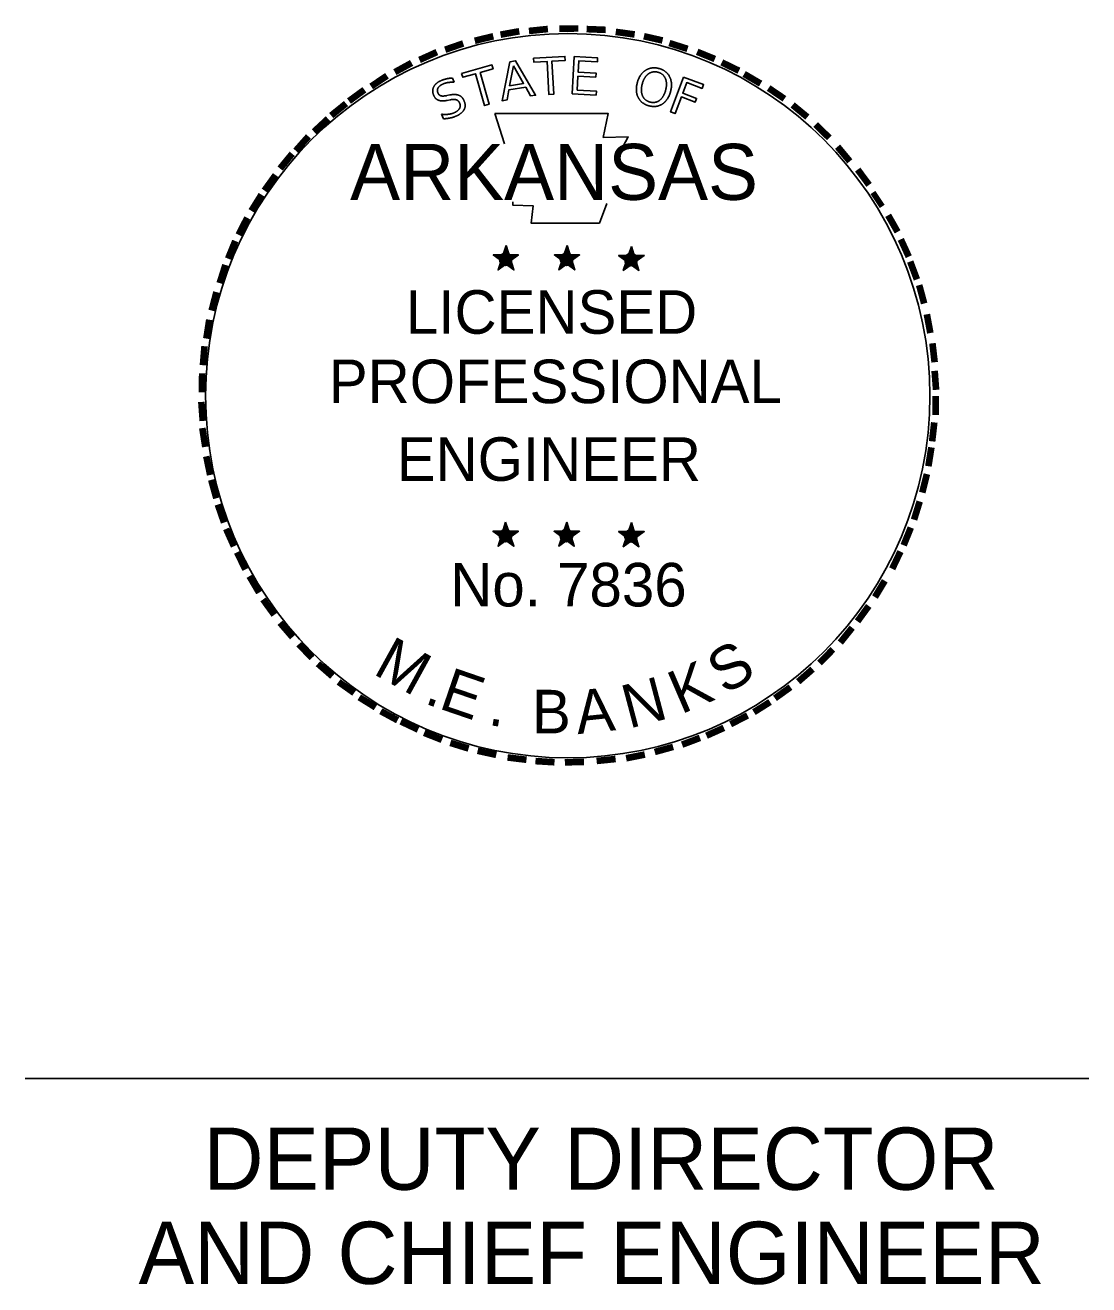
# Model space of a CAD drawing. Extents: x -0.25 to 1.92, y 0 to 0.95.
# Drawn here: x 1.7484 to 1.9193, y 0.0415 to 0.244 of the extents above; entities that cross this region are included whole.
import ezdxf

# ---------------------------------------------------------------- set-up
doc = ezdxf.new("R2010")
doc.units = 0
doc.layers.add('SHET_Stamp-PE-Chief-Eng', color=7, linetype='Continuous')

msp = doc.modelspace()

# ---------------------------------------------------------------- linework, layer by layer
at = {"layer": 'SHET_Stamp-PE-Chief-Eng'}
for p, q in [((1.85025, 0.23705), (1.85025, 0.23705)), ((1.81706, 0.23552), (1.81734, 0.23483)), ((1.85009, 0.23645), (1.85009, 0.23645)), ((1.81617, 0.23269), (1.81666, 0.23279)), ((1.81673, 0.23202), (1.81623, 0.23192)), ((1.81562, 0.22896), (1.81532, 0.2297)), ((1.82568, 0.20858), (1.82544, 0.20707)), ((1.82568, 0.20641), (1.82568, 0.20858)), ((1.82568, 0.20858), (1.82598, 0.20713)), ((1.83551, 0.20858), (1.83527, 0.20707)), ((1.83551, 0.20641), (1.83551, 0.20858)), ((1.83551, 0.20858), (1.83576, 0.20713)), ((1.82363, 0.20707), (1.82568, 0.20641)), ((1.82363, 0.20707), (1.82513, 0.20683)), ((1.82363, 0.20707), (1.82501, 0.20635)), ((1.82767, 0.20707), (1.82568, 0.20641)), ((1.82767, 0.20707), (1.82604, 0.20677)), ((1.82767, 0.20707), (1.82652, 0.20647)), ((1.83346, 0.20707), (1.83551, 0.20641)), ((1.83346, 0.20707), (1.83491, 0.20683)), ((1.83346, 0.20707), (1.83479, 0.20635)), ((1.83751, 0.20707), (1.83551, 0.20641)), ((1.83751, 0.20707), (1.83582, 0.20677)), ((1.83751, 0.20707), (1.8363, 0.20647)), ((1.84378, 0.20701), (1.84583, 0.20635)), ((1.84378, 0.20701), (1.84523, 0.20671)), ((1.84378, 0.20701), (1.84517, 0.20629)), ((1.84583, 0.20846), (1.84559, 0.20701)), ((1.84583, 0.20635), (1.84583, 0.20846)), ((1.84583, 0.20846), (1.84608, 0.20701)), ((1.84789, 0.20701), (1.84583, 0.20635)), ((1.84789, 0.20701), (1.84614, 0.20671)), ((1.84789, 0.20701), (1.84662, 0.20641)), ((1.82441, 0.20466), (1.82568, 0.20641)), ((1.82441, 0.20466), (1.82513, 0.20611)), ((1.82441, 0.20466), (1.82562, 0.20593)), ((1.82694, 0.20466), (1.82562, 0.20593)), ((1.82694, 0.20466), (1.82568, 0.20641)), ((1.82694, 0.20466), (1.8261, 0.20635)), ((1.83419, 0.20466), (1.83551, 0.20641)), ((1.83419, 0.20466), (1.83497, 0.20611)), ((1.83419, 0.20466), (1.83545, 0.20593)), ((1.83672, 0.20466), (1.83545, 0.20593)), ((1.83672, 0.20466), (1.83551, 0.20641)), ((1.83672, 0.20466), (1.83588, 0.20635)), ((1.84451, 0.2046), (1.84583, 0.20635)), ((1.84451, 0.2046), (1.84529, 0.20605)), ((1.84451, 0.2046), (1.84583, 0.20587)), ((1.84704, 0.2046), (1.84583, 0.20635)), ((1.84704, 0.2046), (1.84583, 0.20587)), ((1.84704, 0.2046), (1.84626, 0.20629)), ((1.82562, 0.1641), (1.82538, 0.16266)), ((1.82562, 0.16199), (1.82562, 0.1641)), ((1.82562, 0.1641), (1.82592, 0.16266)), ((1.83545, 0.1641), (1.83521, 0.16266)), ((1.83545, 0.16199), (1.83545, 0.1641)), ((1.83545, 0.1641), (1.8357, 0.16266)), ((1.84583, 0.16404), (1.84559, 0.1626)), ((1.84583, 0.16193), (1.84583, 0.16404)), ((1.84583, 0.16404), (1.84608, 0.1626)), ((1.82357, 0.16266), (1.82562, 0.16199)), ((1.82357, 0.16266), (1.82513, 0.16235)), ((1.82357, 0.16266), (1.82501, 0.16193)), ((1.82441, 0.16024), (1.82562, 0.16199)), ((1.82767, 0.16266), (1.82562, 0.16199)), ((1.82694, 0.16024), (1.82562, 0.16199)), ((1.82767, 0.16266), (1.82598, 0.16235)), ((1.82767, 0.16266), (1.82652, 0.16205)), ((1.8334, 0.16266), (1.83545, 0.16199)), ((1.8334, 0.16266), (1.83491, 0.16235)), ((1.8334, 0.16266), (1.83479, 0.16193)), ((1.83419, 0.16024), (1.83545, 0.16199)), ((1.83751, 0.16266), (1.83545, 0.16199)), ((1.83666, 0.16024), (1.83545, 0.16199)), ((1.83751, 0.16266), (1.83576, 0.16235)), ((1.83751, 0.16266), (1.83624, 0.16205)), ((1.84378, 0.1626), (1.84583, 0.16193)), ((1.84378, 0.1626), (1.84523, 0.16229)), ((1.84378, 0.1626), (1.84517, 0.16187)), ((1.84789, 0.1626), (1.84583, 0.16193)), ((1.84789, 0.1626), (1.84614, 0.16229)), ((1.84789, 0.1626), (1.84662, 0.16199)), ((1.82441, 0.16024), (1.82513, 0.16169)), ((1.82441, 0.16024), (1.82562, 0.16157)), ((1.82694, 0.16024), (1.82562, 0.16151)), ((1.82694, 0.16024), (1.8261, 0.16193)), ((1.83419, 0.16024), (1.83491, 0.16169)), ((1.83419, 0.16024), (1.83545, 0.16157)), ((1.83666, 0.16024), (1.83545, 0.16151)), ((1.83666, 0.16024), (1.83588, 0.16193)), ((1.84451, 0.16018), (1.84583, 0.16193)), ((1.84451, 0.16018), (1.84529, 0.16163)), ((1.84451, 0.16018), (1.84583, 0.16151)), ((1.84704, 0.16018), (1.84583, 0.16193)), ((1.84704, 0.16018), (1.84583, 0.16145)), ((1.84704, 0.16018), (1.8462, 0.16187)), ((1.74841, 0.07469), (1.91934, 0.07469))]:
    msp.add_line(p, q, dxfattribs=at)
for points in [[(1.83012, 0.23872), (1.83516, 0.23899), (1.8352, 0.23835), (1.83306, 0.23823), (1.83335, 0.23291), (1.83258, 0.23286), (1.83229, 0.23819), (1.83015, 0.23807)], [(1.83664, 0.23896), (1.8404, 0.23876), (1.84037, 0.23811), (1.83738, 0.23827), (1.83729, 0.23645), (1.84015, 0.2363), (1.84011, 0.23566), (1.83725, 0.23581), (1.83714, 0.23359), (1.8402, 0.23343), (1.84016, 0.23278), (1.83633, 0.23298)], [(1.81855, 0.23625), (1.82342, 0.23762), (1.82359, 0.237), (1.82153, 0.23642), (1.82298, 0.23129), (1.82223, 0.23108), (1.82078, 0.23621), (1.81873, 0.23563)], [(1.82632, 0.23814), (1.82504, 0.23187), (1.82584, 0.232), (1.82613, 0.23361), (1.82884, 0.23406), (1.82964, 0.23263), (1.83043, 0.23276), (1.82721, 0.23829)], [(1.82688, 0.2375), (1.8285, 0.23465), (1.82626, 0.23428)], [(1.85423, 0.23566), (1.85743, 0.23446), (1.8572, 0.23385), (1.85472, 0.23478), (1.85409, 0.23308), (1.85632, 0.23225), (1.8561, 0.23164), (1.85386, 0.23248), (1.85286, 0.22979), (1.85213, 0.23006)]]:
    msp.add_lwpolyline(points, close=True, dxfattribs=at)
for points in [[(1.82387, 0.22982), (1.82544, 0.22494)], [(1.84445, 0.22445), (1.84529, 0.22608), (1.84131, 0.22596), (1.84209, 0.22982), (1.82387, 0.22982)], [(1.82676, 0.21564), (1.82676, 0.2151), (1.83002, 0.21498), (1.82972, 0.2122), (1.8407, 0.2122), (1.84191, 0.21534)], [(1.82568, 0.20858), (1.82694, 0.20466), (1.82363, 0.20707), (1.82767, 0.20707), (1.82441, 0.20466), (1.82568, 0.20858)], [(1.83551, 0.20858), (1.83672, 0.20466), (1.83346, 0.20707), (1.83751, 0.20707), (1.83419, 0.20466), (1.83551, 0.20858)], [(1.84583, 0.20846), (1.84704, 0.2046), (1.84378, 0.20701), (1.84789, 0.20701), (1.84451, 0.2046), (1.84583, 0.20846)], [(1.82562, 0.1641), (1.82694, 0.16024), (1.82357, 0.16266), (1.82767, 0.16266), (1.82441, 0.16024), (1.82562, 0.1641)], [(1.83545, 0.1641), (1.83666, 0.16024), (1.8334, 0.16266), (1.83751, 0.16266), (1.83419, 0.16024), (1.83545, 0.1641)], [(1.84583, 0.16404), (1.84704, 0.16018), (1.84378, 0.1626), (1.84789, 0.1626), (1.84451, 0.16018), (1.84583, 0.16404)]]:
    msp.add_lwpolyline(points, dxfattribs=at)
for centre, radius in [((1.8356, 0.18445), 0.05821), ((1.82562, 0.2064), 0.00101), ((1.82562, 0.2064), 0.000848), ((1.82562, 0.2064), 0.000679), ((1.82562, 0.2064), 0.000581), ((1.82562, 0.2064), 0.000438), ((1.82562, 0.2064), 0.000291), ((1.82562, 0.2064), 0.000174), ((1.83542, 0.2064), 0.00101), ((1.83542, 0.2064), 0.000848), ((1.83542, 0.2064), 0.000679), ((1.83542, 0.2064), 0.000581), ((1.83542, 0.2064), 0.000438), ((1.83542, 0.2064), 0.000291), ((1.83542, 0.2064), 0.000174), ((1.84577, 0.20633), 0.00101), ((1.84577, 0.20633), 0.000848), ((1.84577, 0.20633), 0.000679), ((1.84577, 0.20633), 0.000581), ((1.84577, 0.20633), 0.000438), ((1.84577, 0.20633), 0.000291), ((1.84577, 0.20633), 0.000174), ((1.8256, 0.16198), 0.00101), ((1.8256, 0.16198), 0.000848), ((1.8256, 0.16198), 0.000679), ((1.8256, 0.16198), 0.000581), ((1.8256, 0.16198), 0.000438), ((1.8256, 0.16198), 0.000291), ((1.8256, 0.16198), 0.000174), ((1.83539, 0.16198), 0.00101), ((1.83539, 0.16198), 0.000848), ((1.83539, 0.16198), 0.000679), ((1.83539, 0.16198), 0.000581), ((1.83539, 0.16198), 0.000438), ((1.83539, 0.16198), 0.000291), ((1.83539, 0.16198), 0.000174), ((1.84575, 0.16192), 0.00101), ((1.84575, 0.16192), 0.000848), ((1.84575, 0.16192), 0.000679), ((1.84575, 0.16192), 0.000581), ((1.84575, 0.16192), 0.000438), ((1.84575, 0.16192), 0.000291), ((1.84575, 0.16192), 0.000174)]:
    msp.add_circle(centre, radius, dxfattribs=at)
for points in [[(1.85025, 0.23705), (1.84903, 0.23737), (1.84809, 0.23675)], [(1.85198, 0.23572), (1.85147, 0.23673), (1.85025, 0.23705)], [(1.81408, 0.23414), (1.81442, 0.23477), (1.81533, 0.23514)], [(1.81533, 0.23514), (1.81572, 0.2353), (1.81616, 0.2354)], [(1.81616, 0.2354), (1.81659, 0.23549), (1.81706, 0.23552)], [(1.84809, 0.23675), (1.84714, 0.23613), (1.84678, 0.23475)], [(1.84757, 0.23455), (1.84786, 0.23566), (1.84854, 0.23617)], [(1.84854, 0.23617), (1.84923, 0.23668), (1.85009, 0.23645)], [(1.85009, 0.23645), (1.85096, 0.23622), (1.85129, 0.23544)], [(1.85129, 0.23544), (1.85163, 0.23466), (1.85133, 0.23355)], [(1.85213, 0.23334), (1.85249, 0.23471), (1.85198, 0.23572)], [(1.81404, 0.23278), (1.81374, 0.23351), (1.81408, 0.23414)], [(1.81479, 0.23397), (1.81455, 0.23359), (1.81473, 0.23313)], [(1.81473, 0.23313), (1.81489, 0.23275), (1.81519, 0.23266)], [(1.81565, 0.2346), (1.81503, 0.23435), (1.81479, 0.23397)], [(1.81643, 0.2348), (1.81601, 0.23475), (1.81565, 0.2346)], [(1.81734, 0.23483), (1.81686, 0.23486), (1.81643, 0.2348)], [(1.81666, 0.23279), (1.81757, 0.23297), (1.81813, 0.23273)], [(1.84678, 0.23475), (1.84641, 0.23338), (1.84693, 0.23238)], [(1.84762, 0.23266), (1.84728, 0.23344), (1.84757, 0.23455)], [(1.85133, 0.23355), (1.85104, 0.23244), (1.85036, 0.23193)], [(1.85082, 0.23135), (1.85176, 0.23197), (1.85213, 0.23334)], [(1.81481, 0.23195), (1.81429, 0.23215), (1.81404, 0.23278)], [(1.81623, 0.23192), (1.81533, 0.23174), (1.81481, 0.23195)], [(1.81519, 0.23266), (1.8155, 0.23256), (1.81617, 0.23269)], [(1.81771, 0.23201), (1.81736, 0.23214), (1.81673, 0.23202)], [(1.81824, 0.23146), (1.81806, 0.23188), (1.81771, 0.23201)], [(1.81813, 0.23273), (1.81869, 0.23249), (1.81896, 0.23182)], [(1.81818, 0.23058), (1.81843, 0.23098), (1.81824, 0.23146)], [(1.81896, 0.23182), (1.81929, 0.23102), (1.81892, 0.23039)], [(1.84693, 0.23238), (1.84744, 0.23137), (1.84866, 0.23105)], [(1.84882, 0.23165), (1.84796, 0.23188), (1.84762, 0.23266)], [(1.84866, 0.23105), (1.84988, 0.23073), (1.85082, 0.23135)], [(1.85036, 0.23193), (1.84969, 0.23142), (1.84882, 0.23165)], [(1.81532, 0.2297), (1.81585, 0.22963), (1.81635, 0.22968)], [(1.81664, 0.22908), (1.81616, 0.22899), (1.81562, 0.22896)], [(1.81635, 0.22968), (1.81685, 0.22973), (1.81728, 0.2299)], [(1.81751, 0.22933), (1.81712, 0.22917), (1.81664, 0.22908)], [(1.81728, 0.2299), (1.81793, 0.23017), (1.81818, 0.23058)], [(1.81892, 0.23039), (1.81855, 0.22976), (1.81751, 0.22933)]]:
    msp.add_open_spline(points, degree=2, dxfattribs=at)

# ---------------------------------------------------------------- texts
for s, height, rotation, p in [('-', 0.00939, 10.2193, (1.82489, 0.23882)), ('-', 0.00939, 5.8968, (1.82918, 0.23942)), ('-', 0.00939, 0.1862, (1.8337, 0.23984)), ('-', 0.00939, 357.743, (1.83793, 0.23978)), ('-', 0.00939, 352.1617, (1.84227, 0.23942)), ('-', 0.00939, 19.1761, (1.81657, 0.23646)), ('-', 0.00939, 13.6301, (1.82097, 0.23785)), ('-', 0.00939, 347.2049, (1.8465, 0.23882)), ('-', 0.00939, 342.3362, (1.8503, 0.23785)), ('-', 0.00939, 24.3072, (1.81276, 0.23489)), ('-', 0.00939, 337.8551, (1.85452, 0.23658)), ('-', 0.00939, 28.7918, (1.80908, 0.23302)), ('-', 0.00939, 334.1211, (1.85827, 0.23501)), ('-', 0.00939, 34.0636, (1.80558, 0.23085)), ('-', 0.00939, 329.6409, (1.86164, 0.23332)), ('-', 0.00939, 36.2317, (1.80214, 0.22856)), ('-', 0.00939, 325.8627, (1.86539, 0.23121)), ('-', 0.00938, 38.9507, (1.79943, 0.22632)), ('-', 0.00939, 320.5297, (1.86901, 0.22874)), ('-', 0.00939, 42.9622, (1.79689, 0.22385)), ('-', 0.00939, 315.5786, (1.87251, 0.22584)), ('-', 0.00939, 48.4231, (1.79424, 0.22101)), ('-', 0.00939, 309.8797, (1.87583, 0.22258)), ('-', 0.00939, 50.6142, (1.79182, 0.21824)), ('-', 0.00939, 306.6522, (1.87896, 0.21908)), ('-', 0.00939, 54.2325, (1.78947, 0.21486)), ('-', 0.00938, 58.0706, (1.78754, 0.21178)), ('-', 0.00821, 303.6753, (1.88174, 0.21576)), ('-', 0.00939, 62.8713, (1.78567, 0.20816)), ('-', 0.00939, 299.6684, (1.88367, 0.21214)), ('-', 0.00938, 67.7743, (1.78416, 0.2046)), ('-', 0.00939, 294.6628, (1.8856, 0.20858)), ('-', 0.00939, 72.3945, (1.78295, 0.20092)), ('-', 0.00939, 290.5728, (1.88705, 0.20526)), ('-', 0.00939, 75.461, (1.78174, 0.19669)), ('-', 0.00939, 285.1233, (1.88844, 0.20182)), ('-', 0.00939, 81.2013, (1.78102, 0.19253)), ('-', 0.00939, 280.5493, (1.88965, 0.19742)), ('-', 0.00939, 85.1863, (1.78054, 0.18849)), ('-', 0.00939, 276.5962, (1.89055, 0.19301)), ('-', 0.00939, 274.3301, (1.89091, 0.18873)), ('-', 0.00939, 89.0622, (1.78042, 0.18438)), ('-', 0.00939, 269.9407, (1.89109, 0.18498)), ('-', 0.00939, 94.1959, (1.7806, 0.1801)), ('-', 0.00939, 263.5172, (1.89097, 0.18112)), ('-', 0.00939, 98.9479, (1.78102, 0.17623)), ('-', 0.00939, 260.9953, (1.89055, 0.17726)), ('-', 0.00939, 101.7149, (1.7818, 0.17189)), ('-', 0.00939, 105.4578, (1.78277, 0.16839)), ('-', 0.00939, 255.7626, (1.88995, 0.17328)), ('-', 0.00939, 109.0874, (1.78398, 0.16471)), ('-', 0.00939, 252.8681, (1.88886, 0.16905)), ('-', 0.00938, 114.0643, (1.78549, 0.16121)), ('-', 0.00939, 247.8887, (1.88759, 0.16513)), ('-', 0.00939, 115.7289, (1.7873, 0.15759)), ('-', 0.00939, 244.6197, (1.88603, 0.16145)), ('-', 0.00939, 120.4471, (1.78941, 0.15415)), ('-', 0.00938, 239.0712, (1.88373, 0.15704)), ('-', 0.00939, 125.8934, (1.7917, 0.15089)), ('-', 0.00939, 233.8452, (1.88138, 0.15324)), ('-', 0.00939, 130.7181, (1.79448, 0.14757)), ('-', 0.00939, 231.2538, (1.87884, 0.14986)), ('-', 0.00939, 134.2238, (1.7975, 0.14443)), ('M', 0.007, 331.1686, (1.80412, 0.13982)), ('S', 0.007, 31.466, (1.86088, 0.13627)), ('-', 0.00938, 225.7653, (1.87601, 0.1466)), ('-', 0.00939, 138.9338, (1.80057, 0.14172)), ('K', 0.007, 23.3052, (1.85378, 0.13317)), ('E', 0.007, 341.04, (1.81467, 0.13424)), ('-', 0.00939, 221.0851, (1.87299, 0.14359)), ('-', 0.00939, 144.6463, (1.80383, 0.1393)), ('N', 0.007, 14.8189, (1.84544, 0.1309)), ('-', 0.00939, 215.7363, (1.86973, 0.14087)), ('-', 0.00939, 148.0898, (1.80709, 0.13713)), ('.', 0.007, 341.04, (1.81238, 0.13503)), ('B', 0.007, 359.9662, (1.82985, 0.13017)), ('A', 0.007, 6.0117, (1.8372, 0.13003)), ('-', 0.00939, 212.2491, (1.86665, 0.13858)), ('-', 0.00939, 151.5704, (1.81047, 0.1352)), ('-', 0.00939, 154.6002, (1.81361, 0.13381)), ('.', 0.007, 350.6464, (1.82267, 0.13156)), ('-', 0.00939, 207.3568, (1.86333, 0.13653)), ('-', 0.00939, 158.5612, (1.81723, 0.1323)), ('-', 0.00939, 200.7184, (1.85609, 0.13303)), ('-', 0.00939, 204.2516, (1.85971, 0.13459)), ('-', 0.00939, 162.7983, (1.82127, 0.13103)), ('-', 0.00939, 167.5555, (1.82544, 0.13013)), ('-', 0.00939, 195.4743, (1.85211, 0.13164)), ('-', 0.00939, 173.1155, (1.82996, 0.12946)), ('-', 0.00939, 176.5183, (1.83425, 0.12911)), ('-', 0.00939, 181.5918, (1.83866, 0.12923)), ('-', 0.00939, 185.8167, (1.84348, 0.12971)), ('-', 0.00939, 191.2858, (1.84783, 0.13043))]:
    msp.add_text(s, height=height, rotation=rotation, dxfattribs=at).set_placement(p)
for s, height, p in [('ARKANSAS', 0.009, (1.80063, 0.21593)), ('LICENSED', 0.007, (1.8096, 0.19441)), ('PROFESSIONAL', 0.007, (1.79721, 0.18325)), ('ENGINEER', 0.007, (1.80812, 0.17076)), ('No. 7836', 0.007, (1.81672, 0.15057)), ('DEPUTY DIRECTOR', 0.01, (1.77705, 0.0568)), ('AND CHIEF ENGINEER', 0.01, (1.76664, 0.04167))]:
    msp.add_text(s, height=height, dxfattribs=at).set_placement(p)

doc.saveas('drawing.dxf')
